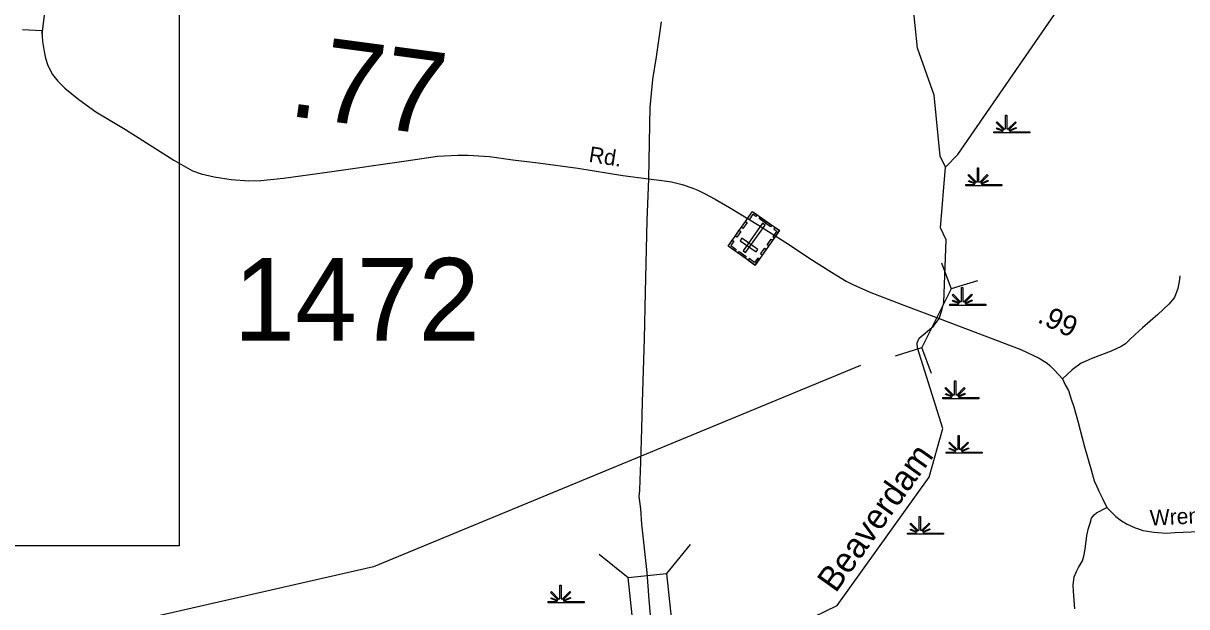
# Model space of a CAD drawing. Extents: x 2093524 to 2270757, y 289120 to 570408.
# Drawn here: x 2111505 to 2118532, y 520328 to 523855 of the extents above; entities that cross this region are included whole.
import ezdxf

# ---------------------------------------------------------------- set-up
doc = ezdxf.new("R2010")
doc.units = 0
for name, color, linetype in [('Exist Cultural Cemetery CELL', 7, 'Continuous'), ('Exist Hydrographic Creek Single Shore', 7, 'Continuous'), ('Exist Hydrographic Creek Single Shore Label', 7, 'Continuous'), ('Exist Hydrographic Swamp CELL', 7, 'Continuous'), ('Exist Road Non-System Type 51', 7, 'Continuous'), ('Exist Road Secondary Mileage Hundredths English Label', 7, 'Continuous'), ('Exist Road Secondary Structure Pipe CELL', 7, 'Continuous'), ('Exist Road Secondary Structure Pipe Number Label', 7, 'Continuous'), ('Exist Road Secondary Structure Standard Bridge CELL', 7, 'Continuous'), ('Exist Road Secondary Type 51 Attributed', 7, 'Continuous'), ('Exist Road Secondary Type 51 Label', 7, 'Continuous'), ('Exist Road Secondary Type 51 Number Label', 7, 'Continuous'), ('Map Preparation Inset Cut Line', 7, 'Continuous')]:
    doc.layers.add(name, color=color, linetype=linetype)

msp = doc.modelspace()

# ---------------------------------------------------------------- linework, layer by layer
at = {"layer": 'Exist Cultural Cemetery CELL'}
for points in [[(2115924.8, 522393.6), (2115762.2, 522508.5), (2115909.1, 522716.4), (2116071.7, 522601.6)], [(2115936.2, 522697.3), (2115929.6, 522687.9), (2115911.6, 522700.6), (2115888.3, 522667.6), (2115879.2, 522674), (2115909.1, 522716.4)], [(2115876.7, 522650.8), (2115851.7, 522615.5), (2115842.4, 522622), (2115867.4, 522657.4)], [(2115852.7, 522480.4), (2115867.9, 522469.7), (2115984.9, 522635.3), (2115969.7, 522646.1)], [(2116018.2, 522625.3), (2115948.9, 522674.3), (2115955.4, 522683.6), (2116024.8, 522634.6)], [(2115838.7, 522597), (2115813.7, 522561.6), (2115804.4, 522568.2), (2115829.4, 522603.6)], [(2116044.7, 522620.6), (2116038.1, 522611.2), (2116056, 522598.5), (2116032.7, 522565.5), (2116041.8, 522559.1), (2116071.7, 522601.5)], [(2115787.2, 522543.9), (2115796.4, 522537.4), (2115777.9, 522511.1), (2115811, 522487.7), (2115804.6, 522478.6), (2115762.2, 522508.5)], [(2115930.7, 522472.7), (2115941.5, 522488), (2115845.4, 522555.9), (2115834.6, 522540.7)], [(2115992.6, 522489.5), (2115967.6, 522454.1), (2115958.3, 522460.7), (2115983.3, 522496.1)], [(2116031.4, 522544.4), (2116006.4, 522509), (2115997.1, 522515.6), (2116022.1, 522551)], [(2115864.3, 522436.3), (2115822, 522466.2), (2115828.6, 522475.6), (2115870.9, 522445.7)], [(2115949.8, 522429), (2115940.5, 522435.5), (2115922, 522409.2), (2115888.8, 522432.6), (2115882.4, 522423.5), (2115924.8, 522393.6)]]:
    msp.add_lwpolyline(points, close=True, dxfattribs=at)
at = {"layer": 'Exist Hydrographic Creek Single Shore'}
for points in [[(2117075.8, 522985.5), (2117041.8, 523051.9), (2117006.7, 523420), (2116905.8, 523704.1), (2116862.8, 524118.4), (2116901.7, 524619.5), (2116975.8, 524926.4), (2117222.8, 525587.3), (2117258.7, 526744.7)], [(2117075.8, 522985.5), (2117149.8, 523062.8), (2117754.7, 523939.7), (2117895.8, 524074.7), (2118401.9, 524441.7), (2118915.8, 524985.8), (2119181.9, 525203.5), (2119486, 525656.6), (2119606, 525763), (2119708.8, 525821.3), (2119809.9, 525847), (2119881.9, 525855.6), (2119926.5, 525853.9), (2119988.2, 525841.9), (2120037.9, 525840.1), (2120103.5, 525846.2)], [(2116212.8, 520234.2), (2116420.9, 520335), (2116975.8, 521111.2), (2117057.8, 521404.7), (2116905.9, 521893.5), (2116903.3, 521922.6), (2116916.2, 521951.8), (2117002.7, 522024.7), (2117036.2, 522070.1), (2117052.4, 522118.2), (2117064.4, 522167.9), (2117077.9, 522546), (2117043.8, 522618.8), (2117075.8, 522985.5)]]:
    msp.add_lwpolyline(points, dxfattribs=at)
at = {"layer": 'Exist Hydrographic Swamp CELL'}
for points in [[(2117367, 523199.3), (2117419.7, 523199.3), (2117421.7, 523202.9), (2117383.4, 523217.8), (2117386.3, 523223), (2117424, 523207.2), (2117425.6, 523210.1), (2117381.2, 523254.7), (2117386.3, 523259.8), (2117431.6, 523214.3), (2117437.9, 523216.7), (2117437.9, 523299.8), (2117445.2, 523299.8), (2117445.2, 523216.7), (2117451.5, 523214.3), (2117496.8, 523259.8), (2117501.9, 523254.7), (2117457.5, 523210.1), (2117459.5, 523206.5), (2117500.4, 523225.1), (2117502.8, 523220.1), (2117461.9, 523202.3), (2117463.5, 523199.3), (2117584.5, 523199.3), (2117584.5, 523192.2), (2117367, 523192.2)], [(2117196.8, 522880.1), (2117249.4, 522880.2), (2117251.4, 522883.8), (2117213.2, 522898.7), (2117216.1, 522903.8), (2117253.8, 522888.1), (2117255.4, 522891), (2117211, 522935.5), (2117216.1, 522940.6), (2117261.4, 522895.2), (2117267.7, 522897.5), (2117267.7, 522980.6), (2117275, 522980.6), (2117275, 522897.5), (2117281.3, 522895.2), (2117326.6, 522940.6), (2117331.7, 522935.5), (2117287.3, 522891), (2117289.3, 522887.4), (2117330.2, 522906), (2117332.6, 522900.9), (2117291.7, 522883.1), (2117293.3, 522880.2), (2117414.3, 522880.1), (2117414.3, 522873), (2117196.8, 522873)], [(2117101.1, 522156.8), (2117153.7, 522156.8), (2117155.7, 522160.4), (2117117.5, 522175.3), (2117120.4, 522180.5), (2117158.1, 522164.7), (2117159.7, 522167.6), (2117115.3, 522212.1), (2117120.4, 522217.3), (2117165.7, 522171.8), (2117172, 522174.2), (2117172, 522257.3), (2117179.3, 522257.3), (2117179.2, 522174.2), (2117185.6, 522171.8), (2117230.9, 522217.3), (2117236, 522212.1), (2117191.6, 522167.6), (2117193.6, 522164), (2117234.5, 522182.6), (2117236.9, 522177.6), (2117195.9, 522159.7), (2117197.5, 522156.8), (2117318.6, 522156.8), (2117318.6, 522149.6), (2117101.1, 522149.6)], [(2117058.5, 521592.9), (2117111.2, 521593), (2117113.2, 521596.6), (2117074.9, 521611.5), (2117077.8, 521616.6), (2117115.5, 521600.9), (2117117.1, 521603.8), (2117072.7, 521648.3), (2117077.8, 521653.5), (2117123.1, 521608), (2117129.4, 521610.4), (2117129.4, 521693.4), (2117136.7, 521693.4), (2117136.7, 521610.4), (2117143, 521608), (2117188.3, 521653.5), (2117193.4, 521648.3), (2117149, 521603.8), (2117151, 521600.2), (2117191.9, 521618.8), (2117194.3, 521613.8), (2117153.4, 521595.9), (2117155, 521593), (2117276, 521592.9), (2117276, 521585.8), (2117058.5, 521585.8)], [(2117079.8, 521263.2), (2117132.4, 521263.2), (2117134.4, 521266.8), (2117096.2, 521281.7), (2117099.1, 521286.9), (2117136.8, 521271.1), (2117138.4, 521274), (2117094, 521318.6), (2117099.1, 521323.7), (2117144.4, 521278.2), (2117150.7, 521280.6), (2117150.7, 521363.7), (2117158, 521363.7), (2117157.9, 521280.6), (2117164.3, 521278.2), (2117209.6, 521323.7), (2117214.7, 521318.6), (2117170.3, 521274), (2117172.3, 521270.4), (2117213.2, 521289), (2117215.6, 521284), (2117174.6, 521266.2), (2117176.3, 521263.2), (2117297.3, 521263.2), (2117297.3, 521256.1), (2117079.8, 521256.1)], [(2116845.8, 520773.8), (2116898.4, 520773.9), (2116900.4, 520777.5), (2116862.1, 520792.3), (2116865, 520797.5), (2116902.8, 520781.8), (2116904.4, 520784.7), (2116859.9, 520829.2), (2116865.1, 520834.3), (2116910.4, 520788.8), (2116916.7, 520791.2), (2116916.7, 520874.3), (2116923.9, 520874.3), (2116923.9, 520791.2), (2116930.2, 520788.8), (2116975.6, 520834.3), (2116980.7, 520829.2), (2116936.3, 520784.7), (2116938.3, 520781.1), (2116979.2, 520799.7), (2116981.6, 520794.6), (2116940.6, 520776.8), (2116942.2, 520773.9), (2117063.3, 520773.8), (2117063.3, 520766.7), (2116845.8, 520766.7)], [(2114675.6, 520358.9), (2114728.3, 520359), (2114730.3, 520362.6), (2114692, 520377.5), (2114694.9, 520382.7), (2114732.6, 520366.9), (2114734.2, 520369.8), (2114689.8, 520414.3), (2114694.9, 520419.5), (2114740.2, 520374), (2114746.6, 520376.4), (2114746.6, 520459.4), (2114753.8, 520459.4), (2114753.8, 520376.4), (2114760.1, 520374), (2114805.4, 520419.5), (2114810.6, 520414.3), (2114766.1, 520369.8), (2114768.1, 520366.2), (2114809, 520384.8), (2114811.5, 520379.8), (2114770.5, 520361.9), (2114772.1, 520359), (2114893.1, 520358.9), (2114893.1, 520351.8), (2114675.6, 520351.8)]]:
    msp.add_lwpolyline(points, close=True, dxfattribs=at)
at = {"layer": 'Exist Road Non-System Type 51'}
for points in [[(2118490, 522327.5), (2118487.6, 522305.6), (2118478.5, 522251.8), (2118457.4, 522198.2), (2118424.6, 522156.9), (2118357.4, 522094.2), (2118263.8, 522014.1), (2118220.9, 521973), (2118186.3, 521941.7), (2118161.8, 521918.2), (2118135.5, 521900.7), (2118075, 521873.9), (2117958.1, 521828.3), (2117921.8, 521813), (2117893.5, 521799.6), (2117840.7, 521760.7), (2117781.6, 521705.9)], [(2117855.7, 520316.5), (2117847.8, 520422.7), (2117846.5, 520458.7), (2117851.5, 520508.6), (2117866.2, 520540.3), (2117878.7, 520566), (2117901.5, 520605.6), (2117910, 520633.4), (2117918.9, 520677.2), (2117928.5, 520759), (2117939.4, 520802.8), (2117948, 520832.6), (2117956.7, 520864.4), (2117973.1, 520884.1), (2117987.3, 520895.8), (2118049.9, 520928.6)]]:
    msp.add_lwpolyline(points, dxfattribs=at)
at = {"layer": 'Exist Road Secondary Structure Pipe CELL'}
for p, q in [((2117051.5, 522406.1), (2117108.9, 522249.8)), ((2117268.2, 522298.7), (2117108.9, 522249.8)), ((2117108.9, 522249.8), (2116932.8, 521894.3)), ((2116773.5, 521845.4), (2116932.8, 521894.3)), ((2116990.2, 521737.9), (2116932.8, 521894.3))]:
    msp.add_line(p, q, dxfattribs=at)
at = {"layer": 'Exist Road Secondary Structure Pipe Number Label'}
msp.add_lwpolyline([(2116561.3, 521785.9), (2113621.2, 520570.3), (2107797.7, 519241.6)], dxfattribs=at)
at = {"layer": 'Exist Road Secondary Structure Standard Bridge CELL'}
for p, q in [((2115532.1, 520704.3), (2115389.7, 520528.3)), ((2114983.5, 520646.5), (2115159.4, 520504.1))]:
    msp.add_line(p, q, dxfattribs=at)
msp.add_lwpolyline([(2115389.7, 520528.3), (2115441.6, 520035.3), (2115211.3, 520011.1), (2115159.4, 520504.1)], close=True, dxfattribs=at)
at = {"layer": 'Exist Road Secondary Type 51 Attributed'}
for points in [[(2111991.1, 526750.4), (2112012.8, 526656.9), (2112033.2, 526578.5), (2112042.2, 526526.3), (2112049, 526468.1), (2112052.6, 526446.1), (2112055.7, 526404), (2112053, 526368.1), (2112043.8, 526308.3), (2112030.4, 526238.5), (2111969.2, 525879.8), (2111901.3, 525485.2), (2111857.9, 525218.1), (2111788, 524823.5), (2111742.8, 524568.4), (2111685.9, 524225.6), (2111643.3, 523996.4), (2111624.5, 523854.8), (2111617.1, 523787)], [(2115357.3, 523864.4), (2115327, 523653), (2115306.3, 523515.4), (2115288.9, 523345.8), (2115286.8, 523243.8), (2115280.2, 522914)], [(2111617.5, 523809), (2111499.6, 523815.4)], [(2111617.5, 523809), (2111622.2, 523744.9), (2111631, 523684.7), (2111640.2, 523644.5), (2111653.3, 523600.3), (2111682.2, 523545.7), (2111713.4, 523505.1), (2111756.5, 523462.2), (2111841.2, 523394.5), (2111943.7, 523320.5), (2112121.7, 523212.8), (2112414.7, 523027.6), (2112527.4, 522963.4), (2112579.1, 522944.3), (2112658.7, 522926.7), (2112760.4, 522910.7), (2112868.2, 522902.5), (2112940.2, 522905.1), (2113076.5, 522918.3), (2113341.2, 522955), (2113818.5, 523023.4), (2114007.1, 523051.6), (2114129.2, 523057.1), (2114191.2, 523057.9), (2114321, 523049.3), (2114462.6, 523030.4), (2114614.2, 523011.4), (2114853.5, 522978.6), (2115126.6, 522935.1), (2115280.2, 522914)], [(2115280.2, 522914), (2115271.1, 522662.2), (2115260.4, 522230.5), (2115254.8, 521948.6), (2115243, 521564.9), (2115239.8, 521405), (2115233.7, 521199.2), (2115229.6, 521095.3), (2115226.3, 521031.3), (2115223.6, 520995.4), (2115232, 520919.2), (2115238.2, 520827.1), (2115270.3, 520534.5), (2115283, 520370.3), (2115298.1, 520211.7)], [(2115280.2, 522914), (2115377.9, 522902.1), (2115419.8, 522897.2), (2115485.5, 522879.9), (2115549, 522858.6), (2115578.8, 522846), (2115620.3, 522825.2), (2115683.7, 522791.9), (2115770.7, 522742.2), (2115938.6, 522638.8), (2116132.1, 522514.9), (2116256.4, 522432.4), (2116386.7, 522349.8), (2116475.6, 522296.1), (2116519.2, 522273.2), (2116624.2, 522227.1), (2116806.8, 522157.4), (2117036.2, 522070.1), (2117529.2, 521882.9), (2117640.1, 521830.7), (2117689.5, 521799.7), (2117705.3, 521787.4), (2117732.7, 521758.8), (2117781.6, 521705.9), (2117796.9, 521669.6), (2117818.2, 521635.1), (2117833.1, 521582.8), (2117850.2, 521536.5), (2117874.5, 521450), (2117915.3, 521295.2), (2117954.5, 521156.4), (2117973.2, 521090.1), (2117988.5, 521055.8), (2117999.9, 521027.6), (2118025, 520979.1), (2118049.9, 520928.6), (2118065.6, 520912.2), (2118102.8, 520873.5), (2118138.3, 520846.8), (2118171.9, 520828.1), (2118219.4, 520805.2), (2118235.4, 520800.8), (2118267.1, 520788.2), (2118334.9, 520778.8), (2118406.8, 520773.4), (2118462.8, 520776.3), (2118607, 520783.4)]]:
    msp.add_lwpolyline(points, dxfattribs=at)
at = {"layer": 'Map Preparation Inset Cut Line'}
msp.add_lwpolyline([(2105386.3, 528530.7), (2112445.8, 528530.7), (2112445.8, 520696.4), (2105386.3, 520696.4)], close=True, dxfattribs=at)

# ---------------------------------------------------------------- texts
at = {"layer": 'Exist Hydrographic Creek Single Shore Label'}
msp.add_text('Beaverdam', height=150, rotation=54.43976, dxfattribs=at).set_placement((2116411.7, 520406.8))
at = {"layer": 'Exist Road Secondary Mileage Hundredths English Label'}
for s, height, rotation, p in [('.77', 500, 352.3984, (2113097.7, 523297.1)), ('.99', 125, 334.79373, (2117623.9, 522050.8))]:
    msp.add_text(s, height=height, rotation=rotation, dxfattribs=at).set_placement(p)
at = {"layer": 'Exist Road Secondary Type 51 Label'}
for s, rotation, p in [('Rd.', 350.9497, (2114916.6, 523018.3)), ('Wrench', 2.81871, (2118311.3, 520818.1))]:
    msp.add_text(s, height=95, rotation=rotation, dxfattribs=at).set_placement(p)
at = {"layer": 'Exist Road Secondary Type 51 Number Label'}
msp.add_text('1472', height=500, dxfattribs=at).set_placement((2112775.6, 521936.2))

doc.saveas('drawing.dxf')
